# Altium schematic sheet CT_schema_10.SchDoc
size 277 x 170 mm
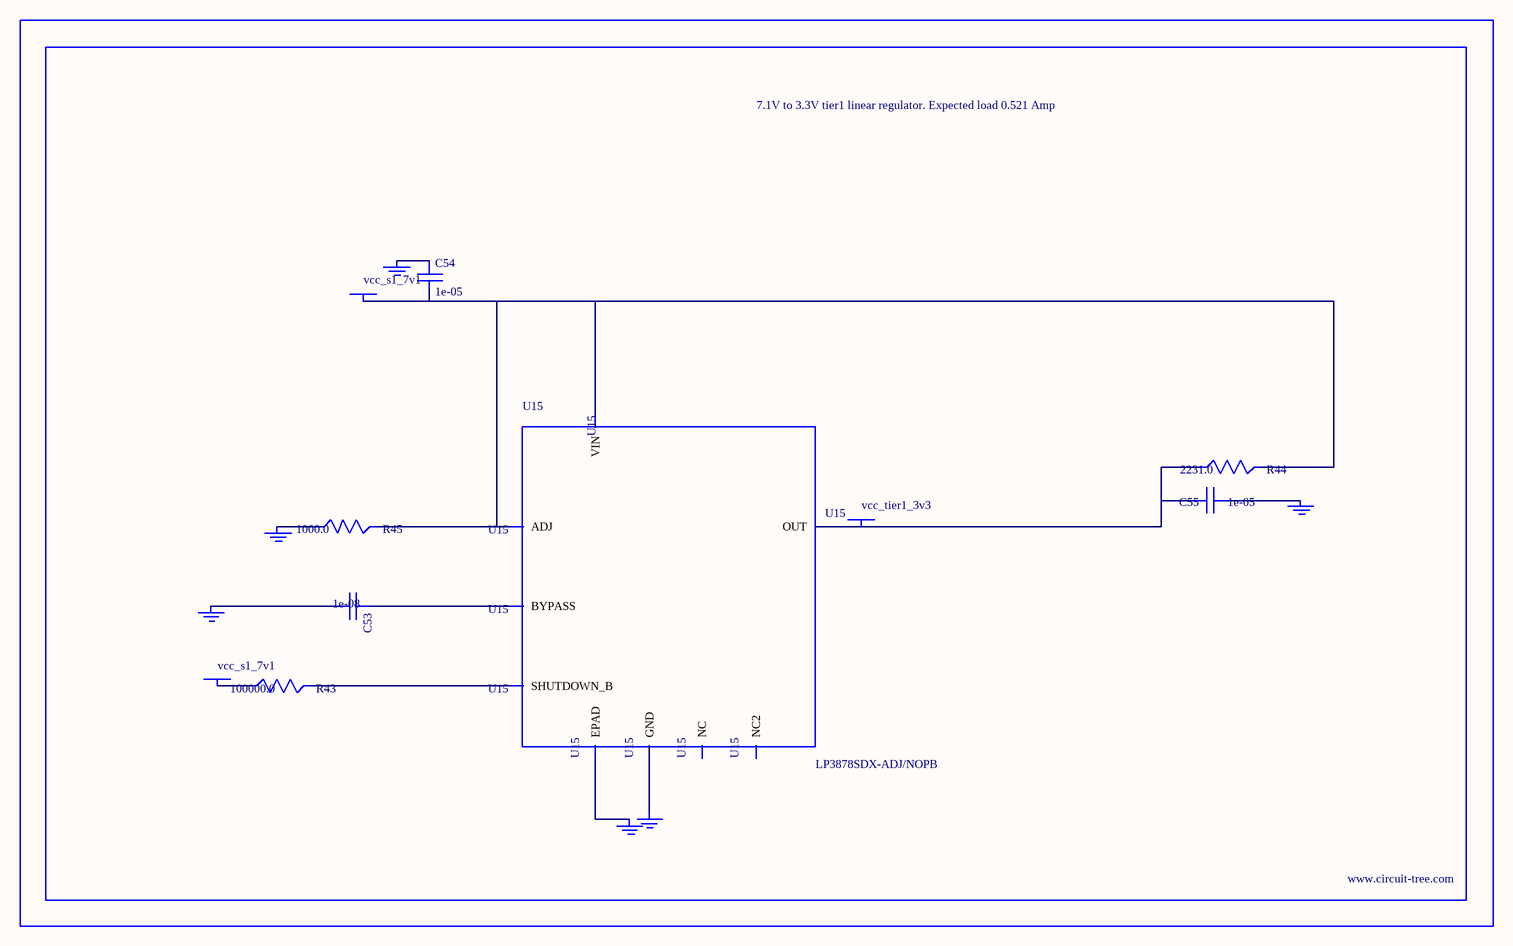
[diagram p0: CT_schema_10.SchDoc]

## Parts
BORDER9  (no value)
C53  1e-08  [C0402]
C54  1e-05  [C1206]
C55  1e-05  [C1210]
GND_INSTANCE_9_0  (no value)
GND_INSTANCE_9_1  (no value)
GND_INSTANCE_9_2  (no value)
GND_INSTANCE_9_3  (no value)
GND_INSTANCE_9_4  (no value)
GND_INSTANCE_9_5  (no value)
POWER_INSTANCE_9_0  vcc_s1_7v1
POWER_INSTANCE_9_1  vcc_s1_7v1
POWER_INSTANCE_9_2  vcc_tier1_3v3
R43  100000.0  [R0603]
R44  2231.0  [R0603]
R45  1000.0  [R0603]
U15  LP3878SDX-ADJ/NOPB  [WSON-8]

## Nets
NetC53_1: C53.1 U15.1(BYPASS)
NetC53_2: C53.2 GND_INSTANCE_9_0.0(GND)
NetC54_1: C54.1 GND_INSTANCE_9_1.0(GND)
NetC54_2: C54.2 POWER_INSTANCE_9_0.0(PWR) R44.2 R45.2 U15.4(VIN) U15.6(ADJ)
NetC55_1: C55.1 GND_INSTANCE_9_2.0(GND)
NetC55_2: C55.2 POWER_INSTANCE_9_2.0(PWR) R44.1 U15.5(OUT)
NetGND_INSTANCE_9_3_0: GND_INSTANCE_9_3.0(GND) R45.1
NetGND_INSTANCE_9_4_0: GND_INSTANCE_9_4.0(GND) U15.PAD(EPAD)
NetGND_INSTANCE_9_5_0: GND_INSTANCE_9_5.0(GND) U15.3(GND)
NetPOWER_INSTANCE_9_1_0: POWER_INSTANCE_9_1.0(PWR) R43.1
NetR43_2: R43.2 U15.8(SHUTDOWN_B)

Not connected (* = marked no-connect by the designer): U15 2(NC) 7(NC2)

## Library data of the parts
BORDER9 = BORDER_PAGE9
C53 = C0402C103K3RAC
C54 = C1206C106K3RACTU
C55 = GRM32DR61E106MA12L
GND_INSTANCE_9_0-GND_INSTANCE_9_5 = GND
POWER_INSTANCE_9_0-POWER_INSTANCE_9_2 = PWR
R43 = RC0603JR-07100KL
R44 = R44
R45 = RC0603JR-071KL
